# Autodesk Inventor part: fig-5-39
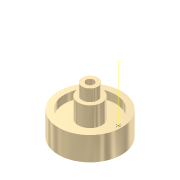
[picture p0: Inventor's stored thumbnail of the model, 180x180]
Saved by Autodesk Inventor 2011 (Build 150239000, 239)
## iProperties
Shininess: 65.0
Length Units: 11269
Angle Units: 11279
Time Units: 11290
Mass Units: 11283
Length Display Precision: 3
Angle Display Precision: 2
Created: 2001-11
Part Number: fig-5-39
Document SubType Name: Modeling
Designer: Renu Muthoo
Density: 1 g/cm^3
Density: 0.0
Volumn: 0.0
Area: 0.0
PropertySet Name: Model Information
Control State: 0
Master: False
Checked Out: False
Author: Renu Muthoo
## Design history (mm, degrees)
sketch "Sketch1"
  geometry: L1 (2.694, 30.112)-(5.194, 30.112); L2 (5.194, 30.112)-(5.194, 22.612); L3 (5.194, 22.612)-(7.694, 22.612); L4 (7.694, 22.612)-(7.694, 10.112); L5 (7.694, 10.112)-(16.444, 10.112); L6 (16.444, 10.112)-(16.444, 15.112); L7 (16.444, 15.112)-(20.194, 15.112); L8 (0.194, -4.034)-(0.194, 25.966); L9 (2.694, 30.112)-(2.694, 0.112); L10 (2.694, 0.112)-(20.194, 0.112); L11 (20.194, 0.112)-(20.194, 15.112)
  constraints: 22 end point, 7 parallel, 2 perpendicular, 1 horizontal
  dimensions: "d0" = 5 diameter of L9 L8; "d1" = 10 diameter of L2 L8; "d2" = 15 diameter of L4 L8; "d3" = 32.5 diameter of L6 L8; "d4" = 40 diameter of L11 L8; "d5" = 15 distance of L10.end L7.end; "d6" = 22.5 distance between parallel lines of L3 L10; "d7" = 30 distance between parallel lines of L1 L10; "d8" = 10 distance between parallel lines of L10 L5
revolve "Revolution1" sketch "Sketch1" stored, may be unused: angle "d9" = 90 deg
workaxis "Work Axis1"
sketch "Sketch2"
  geometry: 1 further point
node "Sketch3"
workaxis "Work Axis3"
body "Solid1"
